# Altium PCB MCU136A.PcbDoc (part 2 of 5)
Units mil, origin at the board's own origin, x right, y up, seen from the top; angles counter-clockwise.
Board outline 3937.01 x 4724.41 mil, 4 copper layers (Top Layer, Signal Layer 1, Signal Layer 2, Bottom Layer), stack 60 mil thick; 390 components, 224 nets, 1130 pads, 1344 vias.
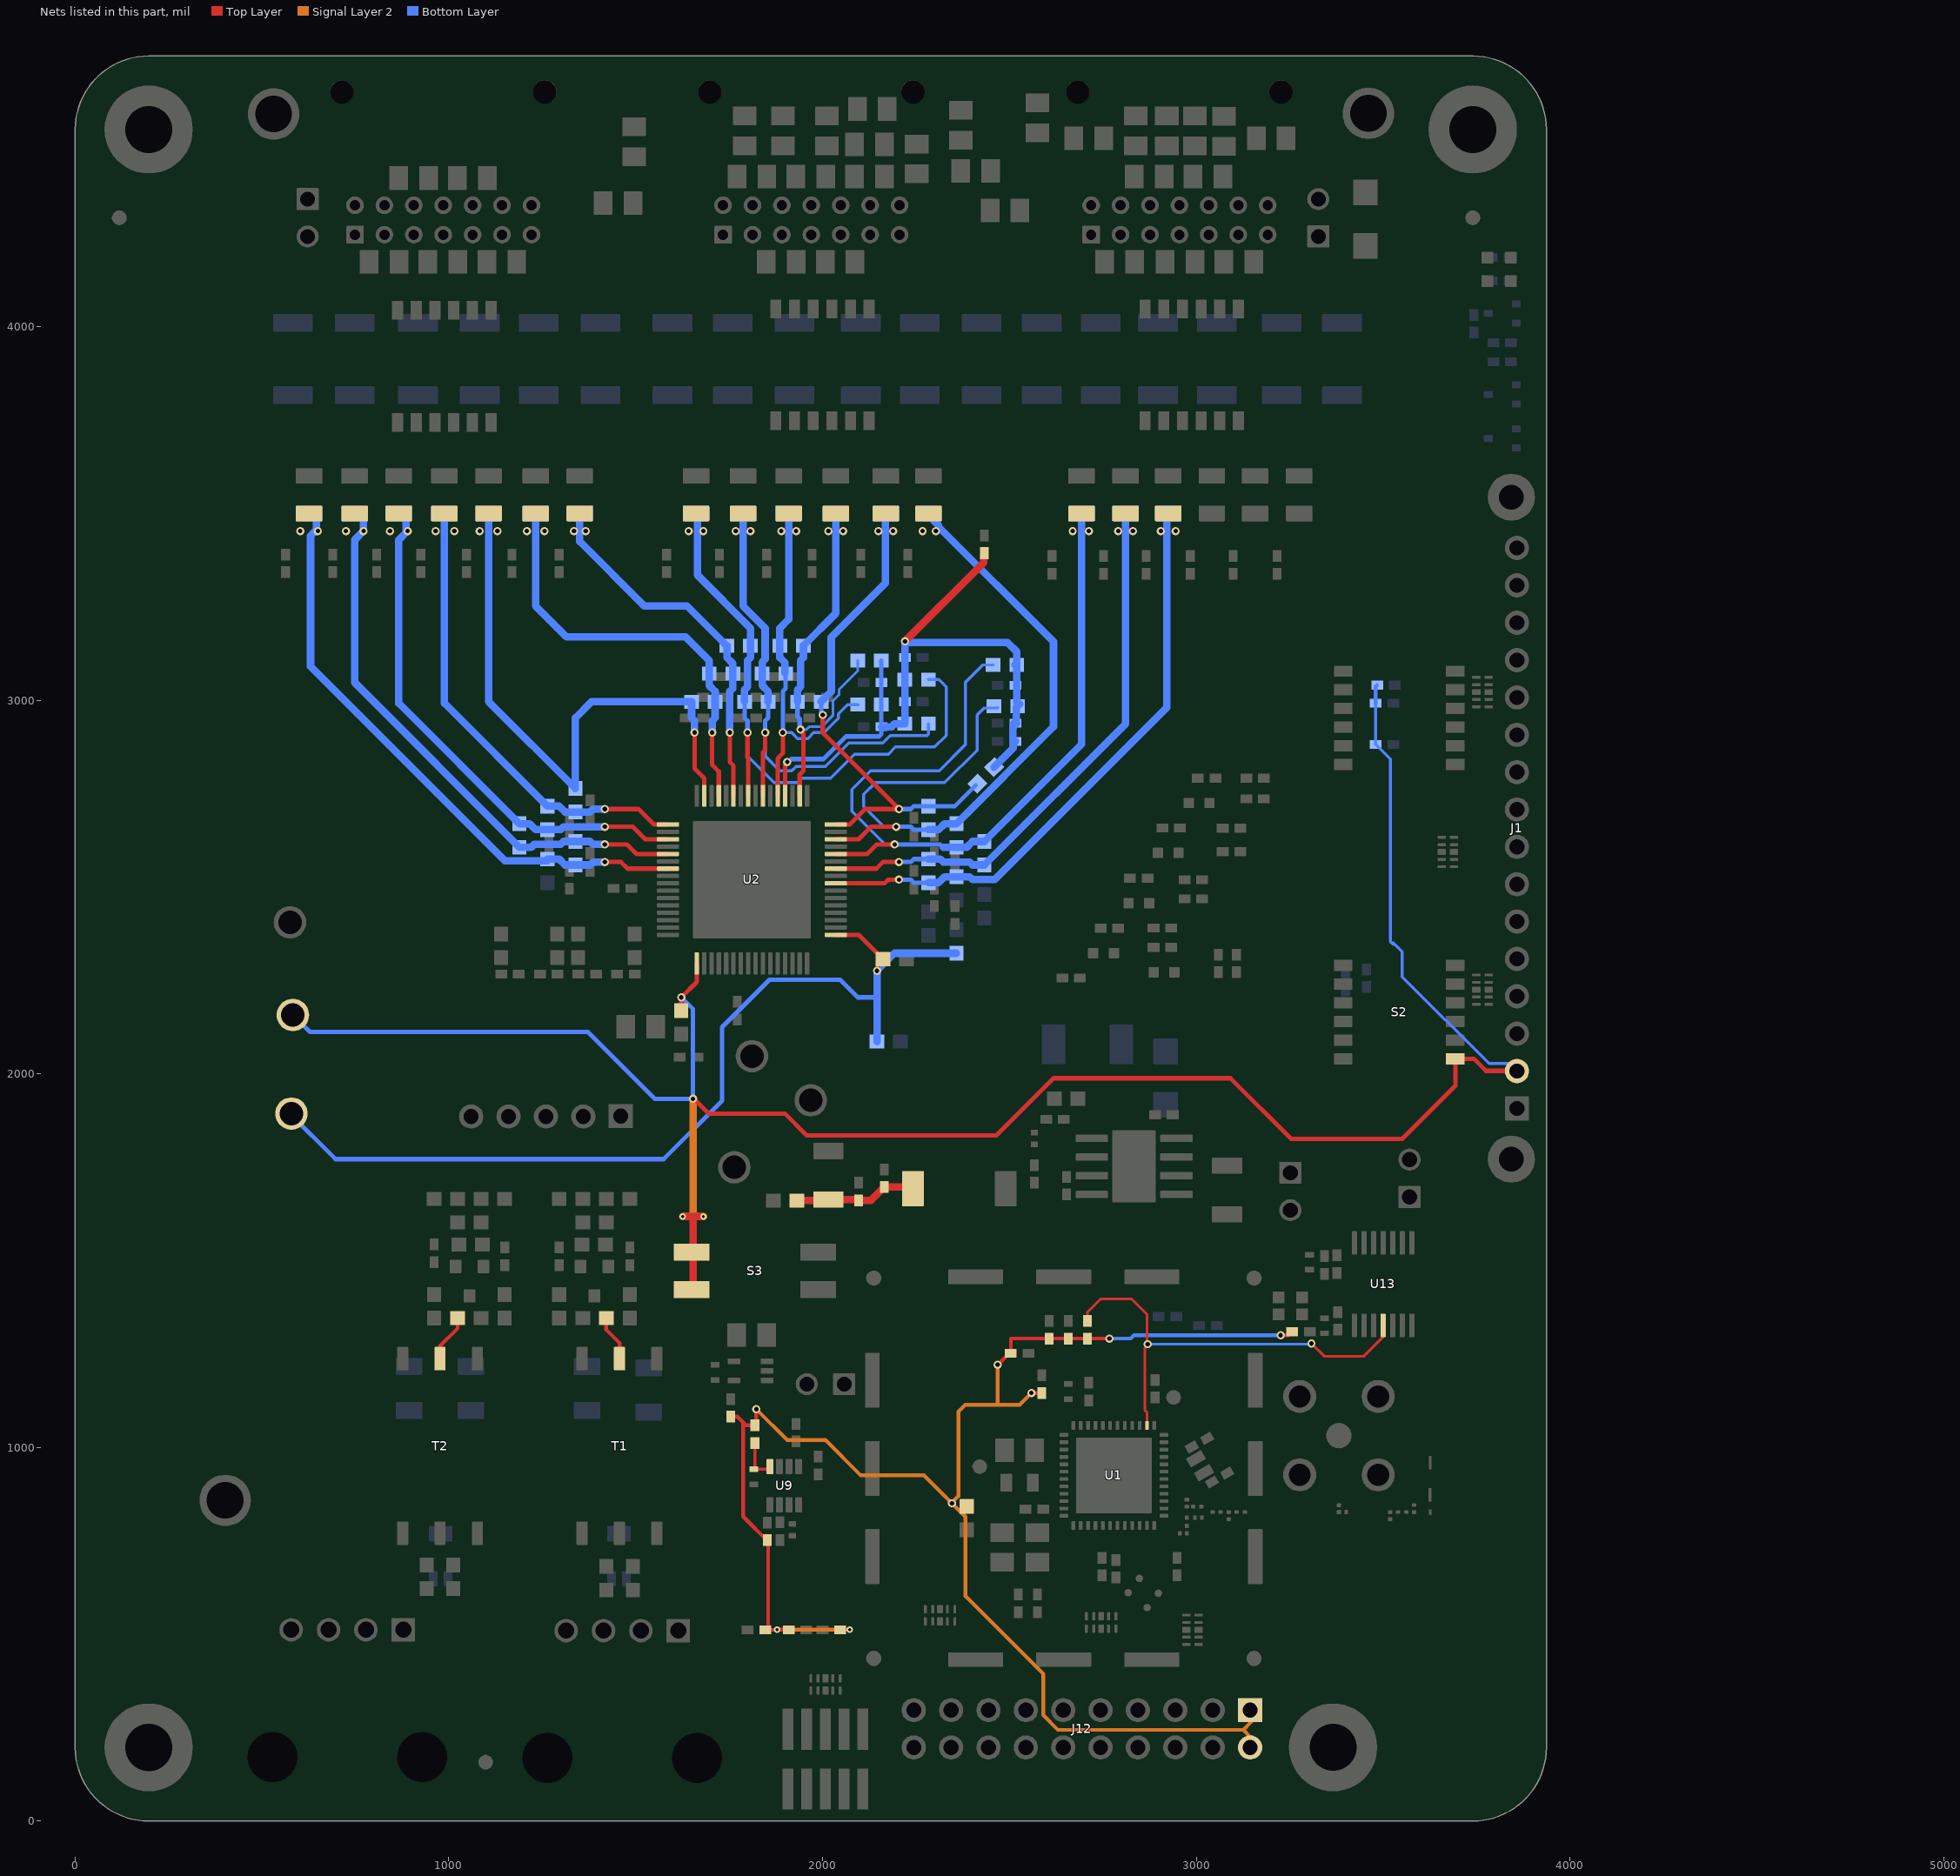
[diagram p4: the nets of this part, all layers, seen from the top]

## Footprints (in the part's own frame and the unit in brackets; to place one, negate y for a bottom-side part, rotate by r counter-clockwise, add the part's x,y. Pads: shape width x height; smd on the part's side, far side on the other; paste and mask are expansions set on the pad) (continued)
FP-SRR0735HA-820M-NO_KEEPOUTS-MFG [mm]
  rrect7% 1.5x2.4 smd paste+0 mask+0: 1(-3.15,0) 2(3.15,0)
  silkscreen extent -3.75,-3.75 3.75,3.75, body extent -3.65,-3.65 3.65,3.65, height 3.7
IEC_HighVoltage_Small [mil]
  silkscreen extent -107,-88 107,97
Keystone1598-2 [mm] "Triple Turret"
  round 3.5 hole 2.5: 1(0,0)
  silkscreen extent -2.08,-2.08 2.08,2.08, body extent -1.6,-1.6 1.59,1.6, height 7.72
Keystone5012 [mil] "Keystone Multipurpose loops"
  round 87 hole 63: 1(0,0)
  body extent -63,-63 63,62, height 319
Molex_70551-0038 [mm] "Header(shrouded), 2.54mm, 4x1, R/A, TH"
  rect 1.6x1.6 hole 1.09: 1(0,3.81)
  round 1.6 hole 1.09: 2(0,1.27) 3(0,-1.27) 4(0,-3.81)
  round 0 hole 3.4 unplated paste-2539.97 mask+0: MH1(8.64,-5.08) MH2(8.64,5.08)
  silkscreen extent 1.45,-6.98 12.88,7.32, body extent -0.71,-6.98 12.88,6.98, height 6.6
PAP0064F-MFG [mm]
  rrect33% 1.5x0.3 smd paste+0 mask+0: 1(-5.7,3.75) 2(-5.7,3.25) 3(-5.7,2.75) 4(-5.7,2.25) 5(-5.7,1.75) 6(-5.7,1.25) 7(-5.7,0.75) 8(-5.7,0.25) 9(-5.7,-0.25) 10(-5.7,-0.75) 11(-5.7,-1.25) 12(-5.7,-1.75) 13(-5.7,-2.25) 14(-5.7,-2.75) 15(-5.7,-3.25) 16(-5.7,-3.75) 33(5.7,-3.75) 34(5.7,-3.25) 35(5.7,-2.75) 36(5.7,-2.25) 37(5.7,-1.75) 38(5.7,-1.25) 39(5.7,-0.75) 40(5.7,-0.25) 41(5.7,0.25) 42(5.7,0.75) 43(5.7,1.25) 44(5.7,1.75) 45(5.7,2.25) 46(5.7,2.75) 47(5.7,3.25) 48(5.7,3.75)
  rrect33% 0.3x1.5 smd paste+0 mask+0: 17(-3.75,-5.7) 18(-3.25,-5.7) 19(-2.75,-5.7) 20(-2.25,-5.7) 21(-1.75,-5.7) 22(-1.25,-5.7) 23(-0.75,-5.7) 24(-0.25,-5.7) 25(0.25,-5.7) 26(0.75,-5.7) 27(1.25,-5.7) 28(1.75,-5.7) 29(2.25,-5.7) 30(2.75,-5.7) 31(3.25,-5.7) 32(3.75,-5.7) 49(3.75,5.7) 50(3.25,5.7) 51(2.75,5.7) 52(2.25,5.7) 53(1.75,5.7) 54(1.25,5.7) 55(0.75,5.7) 56(0.25,5.7) 57(-0.25,5.7) 58(-0.75,5.7) 59(-1.25,5.7) 60(-1.75,5.7) 61(-2.25,5.7) 62(-2.75,5.7) 63(-3.25,5.7) 64(-3.75,5.7)
  rrect1% 8x8 smd paste-1000 mask-1000: 65(0,0)
  silkscreen extent -7.12,-5.1 5.1,5.1, body extent -6.55,-6.55 6.55,6.55, height 0.25
PW0014A-MFG [mm]
  rrect29% 1.6x0.35 smd paste-1000 mask+0: 1(-2.8,1.95) 2(-2.8,1.3) 3(-2.8,0.65) 4(-2.8,0) 5(-2.8,-0.65) 6(-2.8,-1.3) 7(-2.8,-1.95) 8(2.8,-1.95) 9(2.8,-1.3) 10(2.8,-0.65) 11(2.8,0) 12(2.8,0.65) 13(2.8,1.3) 14(2.8,1.95)
  silkscreen extent -4.12,2.27 -3.88,2.52, body extent -3.7,-2.8 3.7,2.8, height 0.25
RGZ0048R-MFG [mm]
  rrect40% 0.6x0.25 smd paste+0 mask+0: 1(-3.4,2.75) 2(-3.4,2.25) 3(-3.4,1.75) 4(-3.4,1.25) 5(-3.4,0.75) 6(-3.4,0.25) 7(-3.4,-0.25) 8(-3.4,-0.75) 9(-3.4,-1.25) 10(-3.4,-1.75) 11(-3.4,-2.25) 12(-3.4,-2.75) 25(3.4,-2.75) 26(3.4,-2.25) 27(3.4,-1.75) 28(3.4,-1.25) 29(3.4,-0.75) 30(3.4,-0.25) 31(3.4,0.25) 32(3.4,0.75) 33(3.4,1.25) 34(3.4,1.75) 35(3.4,2.25) 36(3.4,2.75)
  rrect40% 0.25x0.6 smd paste+0 mask+0: 13(-2.75,-3.4) 14(-2.25,-3.4) 15(-1.75,-3.4) 16(-1.25,-3.4) 17(-0.75,-3.4) 18(-0.25,-3.4) 19(0.25,-3.4) 20(0.75,-3.4) 21(1.25,-3.4) 22(1.75,-3.4) 23(2.25,-3.4) 24(2.75,-3.4) 37(2.75,3.4) 38(2.25,3.4) 39(1.75,3.4) 40(1.25,3.4) 41(0.75,3.4) 42(0.25,3.4) 43(-0.25,3.4) 44(-0.75,3.4) 45(-1.25,3.4) 46(-1.75,3.4) 47(-2.25,3.4) 48(-2.75,3.4)
  rrect2% 5.15x5.15 smd paste-1000 mask+0: 49(0,0)
  silkscreen extent -4.05,-3.55 3.55,3.84, body extent -3.8,-3.8 3.8,3.8, height 0.25
Samtec_FTSH-105-01-x-DV-K [mm] "Header(Shrouded), 1.27mm, 5x2, SMT"
  rect 2.79x0.74 smd: 1(-2.035,2.54) 2(2.035,2.54) 3(-2.035,1.27) 4(2.035,1.27) 5(-2.035,0) 6(2.035,0) 7(-2.035,-1.27) 8(2.035,-1.27) 9(-2.035,-2.54) 10(2.035,-2.54)
  silkscreen extent -3.73,-3.48 3.73,3.48, body extent -2.92,-3.18 2.92,3.17, height 6.13
Samtec_SMA-J-P-H-ST-MT1 [mm] "JACK, SMA, 50 Ohm, TH"
  round 1.73 smd: 1(0,0)
  round 2.25 hole 1.5: 2(-2.665,2.665) 3(2.665,2.665) 4(-2.665,-2.665) 5(2.665,-2.665)
  body extent -3.17,-3.17 3.18,3.18, height 7.95
SNT-100-BK-G [mil] "Samtec STEP model"
  round 1 on Mech3: 0(0,0)
  body extent -100,-50 100,50, height 344
SOT-323 [mm] "Diodes Inc recommended land pattern.  2016-02-24"
  rrect21% 0.6x0.47 smd: 1(-0.95,0.65) 2(-0.95,-0.65) 3(0.95,0)
  silkscreen extent -1.14,-1.22 0.77,1.22, body extent -1.13,-1.13 1.12,1.12, height 1.13
SW_219-2MST [mm] "SMT, 4-Leads, Body 6.55x6.7mm, Pitch 2.54mm"
  rect 2.44x1.13 smd: 1(-4.3,1.27) 2(-4.3,-1.27) 3(4.3,-1.27) 4(4.3,1.27)
  body extent -4.95,-3.28 4.95,3.28, height 4.32
SW_TDA06H0SB1 [mil] "SMT, 12-Lead, Body 8.75x6.2mm, Pitch 1.27mm"
  rect 50x30 smd: 1(-150,125) 2(-150,75) 3(-150,25) 4(-150,-25) 5(-150,-75) 6(-150,-125) 7(150,-125) 8(150,-75) 9(150,-25) 10(150,25) 11(150,75) 12(150,125)
  silkscreen extent -126,-172 126,172, body extent -160,-172 160,172, height 91
TI_Horizontal_Overlay_Small [mil]
  silkscreen extent -545,-68 545,67
TP_SM_1MM#1 [mm] "1mm Test Point, SMT"
  round 1 smd paste-0.5: 1(0,-0.361)
TP_SM_1MM#2 [mm] "1mm Test Point, SMT"
  round 1 smd paste-0.5: 1(0,0.508)
TSW-105-07-X-S [mm] "Samtec 100mil, 1x5, 230 mil above insulator"
  rrect6% 1.65x1.65 hole 1.016: 1(-5.08,-0.025)
  round 1.65 hole 1.016: 2(-2.54,0) 3(0,0) 4(2.54,0) 5(5.08,0)
  silkscreen extent -7.05,-1.25 6.37,1.25, body extent -6.35,-1.27 6.35,1.27, height 8.38
TSW-110-07-G-D [mm] "Samtec 100mil, 2x10, 230 mil above insulator"
  rrect6% 1.65x1.65 hole 1.016: 1(-11.43,-1.27)
  round 1.65 hole 1.016: 2(-11.43,1.27) 3(-8.89,-1.27) 4(-8.89,1.27) 5(-6.35,-1.27) 6(-6.35,1.27) 7(-3.81,-1.27) 8(-3.81,1.27) 9(-1.27,-1.27) 10(-1.27,1.27) 11(1.27,-1.27) 12(1.27,1.27) 13(3.81,-1.27) 14(3.81,1.27) 15(6.35,-1.27) 16(6.35,1.27) 17(8.89,-1.27) 18(8.89,1.27) 19(11.43,-1.27) 20(11.43,1.27)
  silkscreen extent -13.73,-2.54 12.7,2.54, body extent -12.7,-2.54 12.7,2.54, height 8.38
TSW-116-07-G-S [mm] "Samtec 100mil, 1x16, 230 mil above insulator"
  rrect6% 1.65x1.65 hole 1.016: 1(-19.05,0)
  round 1.65 hole 1.016: 2(-16.51,0) 3(-13.97,0) 4(-11.43,0) 5(-8.89,0) 6(-6.35,0) 7(-3.81,0) 8(-1.27,0) 9(1.27,0) 10(3.81,0) 11(6.35,0) 12(8.89,0) 13(11.43,0) 14(13.97,0) 15(16.51,0) 16(19.05,0)
  silkscreen extent -20.39,-1.27 20.32,1.63, body extent -20.32,-1.27 20.32,1.27, height 8.38
WEEE_Minimum [mil] "WEEElie bin"
  silkscreen extent -95,-172 99,104
WL-SMCW_GREEN [mm] "WURTH"
  rect 0.8x0.8 smd: 1(-0.8,0) 2(0.8,0)
  silkscreen extent -1.9,-0.8 1.2,0.8, body extent -0.85,-0.45 0.85,0.45, height 0.8
WL-SMCW_RED [mm] "WURTH"
  rect 0.8x0.8 smd: 1(-0.8,0) 2(0.8,0)
  silkscreen extent -1.9,-0.8 1.2,0.8, body extent -0.85,-0.45 0.85,0.45, height 0.8

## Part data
C1 C8 C10 C15 C16: library part CMP-0006356-2, "CAP, CERM, 0.1 uF, 50 V, +/- 10%, X7R, AEC-Q200 Grade 1, 0402", Cap_Case=0402, Manufacturer=MuRata, Supplier Part Number 1=490-10672-1-ND, TempCo=X7R, Tolerance_%=10%, Value1=Unknown, Value2=50V, ValueDisplayed=0.1uF
C2: library part CMP-0006357-2, "CAP, CERM, 2200 pF, 50 V, +/- 10%, X7R, AEC-Q200 Grade 1, 0402", Cap_Case=0402, Manufacturer=MuRata, Supplier Part Number 1=490-4914-1-ND, TempCo=X7R, Tolerance_%=10%, Value1=Unknown, Value2=50V, ValueDisplayed=2200pF
C3: library part CMP-0096011-1, "Ceramic Capacitor for Automotive 47uF ±10% 10VDC X7S 1210 Embossed T/R", Manufacturer=Murata, Operating Temperature Range="-55°C to +125°C", TempCo=22%, Temperature Characteristic=X7S, Tolerance_%=10%, ValueDisplayed=47uF
C4: library part CMP-0093675-1, "4.7uF ±10% 100V Ceramic Capacitor X7S 1210 (3225 Metric)", Manufacturer=Murata, Operating Temperature Range="-55°C to +125°C", TempCo=22%, Temperature Characteristic=X7S, Tolerance_%=10%, ValueDisplayed=4.7uF
C5: library part CMP-0006359-2, "CAP, CERM, 3300 pF, 50 V, +/- 10%, X7R, AEC-Q200 Grade 1, 0402", Cap_Case=0402, Manufacturer=MuRata, Supplier Part Number 1=490-8001-1-ND, TempCo=X7R, Tolerance_%=10%, Value1=Unknown, Value2=50V, ValueDisplayed=3300pF
C6: library part CMP-0121510-1, "Ceramic Capacitor for Automotive 56pF ±1% 50VDC C0G 0402 Paper T/R", Manufacturer=Murata, Operating Temperature Range="-55°C to +125°C", TempCo=30ppm/°C, Temperature Characteristic=C0G, Tolerance_%=0.01%, ValueDisplayed=56pF
C7 C11: library part CMP-0084773-1, "CAP, CERM, 0.01 µF, 100 V,+/- 10%, X7R, AEC-Q200 Grade 1, 0603", Cap_Case=0603, Manufacturer=MuRata, TempCo=X7R, Tolerance_%=10%, Value2=100V, ValueDisplayed=0.01µF
C9 C14 C17: library part CMP-0064967-2, "CAP, CERM, 0.47 uF, 10 V,+/- 10%, X7S, 0402", Cap_Case=0402, Manufacturer=MuRata, Supplier Part Number 1=490-14427-1-ND, TempCo=X7S, Tolerance_%=10%, Value1=Unknown, Value2=10V, ValueDisplayed=0.47uF
C12: library part CMP-0860704-1, "CAP, CERM, 1 µF, 25 V,+/- 10%, X8L, AEC-Q200 Grade 0, 0805", Cap_Case=0805, Manufacturer=MuRata, TempCo=X8L, Tolerance_%=10%, Value2=25V, ValueDisplayed=1µF
C13: library part CMP-0007136-5, "CAP, CERM, 1 uF, 16 V, +/- 10%, X7R, AEC-Q200 Grade 1, 0603", Cap_Case=0603, Manufacturer=MuRata, Supplier Part Number 1=490-5241-6-ND, TempCo=X7R, Tolerance_%=10%, Value1=Unknown, Value2=16V, ValueDisplayed=1uF
C18 C19 C21 C23 C25 C27 C29 C31 C33 C35 C37 C42 C47 C48 C52 C57 C61 C63 C65 C67 C69: library part CMP-0007144-4, "CAP, CERM, 0.1 uF, 50 V, +/- 10%, X7R, 0603", Cap_Case=0603, Manufacturer=MuRata, Supplier Part Number 1=490-4779-1-ND, TempCo=X7R, Tolerance_%=10%, Value1="0.02 ohm", Value2=50V, ValueDisplayed=0.1uF
C20 C22 C24 C26 C28 C30 C32 C34 C36 C39 C44 C49 C50 C54 C58 C62 C64 C66 C68 C70: library part CMP-0006361-2, "CAP, CERM, 4700 pF, 50 V, +/- 10%, X7R, AEC-Q200 Grade 1, 0402", Cap_Case=0402, Manufacturer=MuRata, Supplier Part Number 1=490-4915-1-ND, TempCo=X7R, Tolerance_%=10%, Value1=Unknown, Value2=50V, ValueDisplayed=4700pF
C38 C41 C45 C51 C55 C60: library part CMP-0007144-4, "CAP, CERM, 0.1 uF, 50 V, +/- 10%, X7R, 0603", Cap_Case=0603, Manufacturer=MuRata, Supplier Part Number 1=490-4779-1-ND, TempCo=X7R, Tolerance_%=10%, Value1="0.02 ohm", Value2=50V, ValueDisplayed=DNP
C40 C43 C46 C53 C56 C59: library part CMP-0006361-2, "CAP, CERM, 4700 pF, 50 V, +/- 10%, X7R, AEC-Q200 Grade 1, 0402", Cap_Case=0402, Manufacturer=MuRata, Supplier Part Number 1=490-4915-1-ND, TempCo=X7R, Tolerance_%=10%, Value1=Unknown, Value2=50V, ValueDisplayed=DNP
C71 C76 C77 C82: library part CMP-0090879-1, "2200pF ±10% 2000V (2kV) Ceramic Capacitor X7R (2R1) 1206 (3216 Metric)", Digikey Part Number=1608-1486-1-ND, Manufacturer="Knowles Syfer", Mouser Part Number=843-1206Y2K00222KET, Operating Temperature Range="-55°C to +125°C", TempCo=15%, Temperature Characteristic=X7R, Tolerance_%=10%, ValueDisplayed=2.2nF
C72 C75 C78 C81: library part CMP-0006316-2, "CAP, CERM, 220 pF, 50 V, +/- 10%, X7R, AEC-Q200 Grade 1, 0402", Cap_Case=0402, Manufacturer=TDK, Supplier Part Number 1=445-6886-1-ND, TempCo=X7R, Tolerance_%=10%, Value1="9.829 ohm", Value2=50V, ValueDisplayed=220pF
C73 C79: library part CMP-0007143-4, "CAP, CERM, 0.01 uF, 50 V, +/- 10%, X7R, AEC-Q200 Grade 1, 0603", Cap_Case=0603, Manufacturer=MuRata, Supplier Part Number 1=490-4778-1-ND, TempCo=X7R, Tolerance_%=10%, Value1=Unknown, Value2=50V, ValueDisplayed=0.01uF
C74 C80: library part CMP-0750041-1, "CAP, CERM, 100 pF, 50 V,+/- 5%, C0G/NP0, AEC-Q200 Grade 1, 0603", Cap_Case=0603, Manufacturer=MuRata, TempCo=C0G/NP0, Tolerance_%=5%, Value2=50V, ValueDisplayed=100pF
C83: library part CMP-0120705-1, "Ceramic Capacitor for Automotive 47nF ±10% 25VDC X7R 0402 Paper T/R", Manufacturer=Murata, Operating Temperature Range="-55°C to +125°C", TempCo=15%, Temperature Characteristic=X7R, Tolerance_%=0.1%, ValueDisplayed=47nF
C84 C85 C88 C91 C108: library part CMP-0006349-2, "CAP, CERM, 1 uF, 10 V, +/- 10%, X7S, AEC-Q200 Grade 1, 0402", Cap_Case=0402, Manufacturer=MuRata, Supplier Part Number 1=81-GCM155C71A105KE8D, TempCo=X7S, Tolerance_%=10%, Value1=Unknown, Value2=10V, ValueDisplayed=1uF
C86: library part CMP-0006352-2, "CAP, CERM, 0.01 uF, 25 V, +/- 10%, X7R, 0402", Cap_Case=0402, Manufacturer=MuRata, Supplier Part Number 1=490-6043-2-ND, TempCo=X7R, Tolerance_%=10%, Value1=Unknown, Value2=25V, ValueDisplayed=0.01uF
C87: library part CMP-0083622-1, "CAP, CERM, 2.2 µF, 25 V,+/- 10%, X7R, AEC-Q200 Grade 1, 0805", Cap_Case=0805, Manufacturer=MuRata, Supplier Part Number 1=490-4787-1-ND, TempCo=X7R, Tolerance_%=10%, Value2=25V, ValueDisplayed=2.2µF
C89 C90 C103 C104 C105 C107 C109 C111 C112: library part CMP-0006350-2, "CAP, CERM, 0.1 uF, 10 V, +/- 10%, X7R, AEC-Q200 Grade 1, 0402", Cap_Case=0402, Manufacturer=MuRata, Supplier Part Number 1=81-GCM155R71A104K5D, TempCo=X7R, Tolerance_%=10%, Value1=Unknown, Value2=10V, ValueDisplayed=0.1uF
C92: library part CMP-0120430-1, "High Q Chip Multilayer Ceramic Capacitors for Automotive 12pF ±2% 50Vdc 0201", Manufacturer=Murata, Operating Temperature Range="-25°C to +125°C", TempCo=30ppm/°C, Temperature Characteristic=C0G, Tolerance_%=2%, ValueDisplayed=DNP
C93 C97: library part CMP-0120430-1, "High Q Chip Multilayer Ceramic Capacitors for Automotive 12pF ±2% 50Vdc 0201", Manufacturer=Murata, Operating Temperature Range="-25°C to +125°C", TempCo=30ppm/°C, Temperature Characteristic=C0G, Tolerance_%=2%, ValueDisplayed=12pF
C94 C95: library part CMP-0085816-1, "CAP, CERM, 12 pF, 50 V,+/- 5%, C0G/NP0, AEC-Q200 Grade 1, 0402", Cap_Case=0402, Manufacturer=MuRata, TempCo=C0G/NP0, Tolerance_%=5%, Value2=50V, ValueDisplayed=12pF
C96 C99 C101: library part CMP-0120431-1, "1pF ±0.05pF 50V Ceramic Capacitor C0G 0201 (0603 Metric)", Manufacturer=Murata, Operating Temperature Range="-55°C to +125°C", TempCo=30ppm/°C, Temperature Characteristic=C0G, ValueDisplayed=1pF
C98: library part CMP-0124483-1, "Cap Ceramic 1.1pF ±0.1pF 50V C0G 0201 AECQ200", Manufacturer=Murata, Operating Temperature Range="-55°C to +125°C", TempCo=30ppm/°C, Temperature Characteristic=C0G, ValueDisplayed=1.1pF
C100: library part CMP-0120431-1, "1pF ±0.05pF 50V Ceramic Capacitor C0G 0201 (0603 Metric)", Manufacturer=Murata, Operating Temperature Range="-55°C to +125°C", TempCo=30ppm/°C, Temperature Characteristic=C0G, ValueDisplayed=DNP
C102 C106 C110: library part CMP-0008015-1, "CAP, CERM, 22 uF, 6.3 V, +/- 20%, X7T, AEC-Q200 Grade 1, 0805", Cap_Case=0805, Manufacturer=MuRata, TempCo=X7T, Tolerance_%=20%, Value1=Unknown, Value2=6.3V, ValueDisplayed=22uF
D1 D4: library part CMP-0121790-1, "137V Clamp 2.9A Ipp Tvs Diode Surface Mount DO-214AC (SMA)", Breakdown Voltage=94.4V, Clamping Voltage=137V, Digikey Part Number=13-SMAJ85A-AT/TR13CT-ND, Manufacturer=YAGEO, Mouser Part Number=603-SMAJ85A-AT/TR13, Operating Temperature Range="-55°C to +150°C"
D2 D5: library part CMP-0002894-2, "LED, Green, SMD", Color=green, Manufacturer="Wurth Elektronik", Value1=W, Value2=2V
D3 D6: library part CMP-0002947-3, "LED, Red, SMD", Color=Red, Manufacturer="Wurth Elektronik", Power_TotalModule=72mW, Value1=0.072W, Value2=2V
E1: library part CMP-0001734-1, "2.4GHz PCB Antenna.  There is nothing to buy or mount.", Manufacturer=N/A
FID1 FID2 FID3 FID4 FID5 FID6: library part CMP-0077181-1, "Fiducial mark.  There is nothing to buy or mount.", Manufacturer=N/A
J1: library part CMP-0075430-1, "Header, 100mil, 16x1, Gold, TH", Color=Black, Current_A=6.3A, Manufacturer=Samtec, Supplier Part Number 1=SAM1029-16-ND, Voltage_V=550V
J2 J6 J11 J13 J14: library part CMP-0002337-1, "Header, 100mil, 2x1, Tin, TH", Color=Black, Current_A=3A, Manufacturer="Sullins Connector Solutions", Supplier Part Number 1=S1012E-02-ND, Voltage_V=1.8kV
J3 J4 J5: library part CMP-0096844-1, "14 Position Dual Row Side Entry 2 mm Through Hole Shrouded Header", Current_A=3A, Digikey Part Number=455-2488-ND, Manufacturer=JST, Operating Temperature Range="-25°C to +85°C", Voltage_V=250V
J7 J9: library part CMP-0055239-1, "Header(shrouded), 2.54mm, 4x1, R/A, Gold, TH", Color=Black, Current_A=3A, Manufacturer=Molex, Supplier Part Number 1=0705510038-ND, Voltage_V=250V
J8: library part CMP-0075411-1, "Header, 100mil, 5x1, Gold, TH", Color=Black, Current_A=6.3A, Manufacturer=Samtec, Supplier Part Number 1=SAM1029-05-ND, Voltage_V=550V
J10: library part CMP-0075670-2, "Header (Shrouded), 1.27mm, 5x2, Gold, SMT", Color=Black, Current_A=3.3A, Manufacturer=Samtec, Supplier Part Number 1=SAM8796-ND
J12: library part CMP-0075421-2, "Header, 100mil, 10x2, Gold, TH", Color=Black, Current_A=6.3A, Manufacturer=Samtec, Supplier Part Number 1=SAM1028-10-ND, Voltage_V=550V
J15: library part CMP-0080462-1, "JACK, SMA, 50 Ohm, Gold, TH", Color=Gold, Manufacturer=Samtec, Supplier Part Number 1=SAM10718-ND, Voltage_V=335V
L1: library part CMP-0125208-2, "82 µH Shielded Drum Core, Wirewound Inductor 630 mA 480mOhm Max Nonstandard", Alternate Manufacturer=Bourns, Alternate PartNumber=SRR0735A-820M, Digikey Part Number=118-SRR0735HA-820MTR-ND, Mouser Part Number=652-SRR0735HA-820M, Operating Temperature Range="-55°C to +150°C", Test Frequency=1kHz, Tolerance_%=20%
L2 L3: library part CMP-0093758-1, "100 µH @ 100 kHz 2 Line Common Mode Choke Surface Mount 150mA DCR 1.5Ohm", Digikey Part Number=445-175063-1-ND, Manufacturer=TDK, Mouser Part Number=810-ACT1210R-101-2P, Operating Temperature Range="-40°C to +125°C", Test Frequency=100kHz, Tolerance_%=+50/-30%
L4 L8: library part CMP-0090225-1, "Inductor 3.7nH, Size Code 0603 (0201), High Q, Wide Variation. AEC-Q200", Manufacturer=Murata, Operating Temperature Range="-55°C to +125°C", Self Resonant Frequency=6GHz, Test Frequency=500MHz, Tolerance_%=0.1nH
L5: library part CMP-0124485-1, "Film type RF Inductor for Automotive 2.2nH ±0.1nH 600mA 0.15Ω 0201 (0603)", Manufacturer=Murata, Operating Temperature Range="-55°C to +125°C", Self Resonant Frequency=11GHz, Test Frequency=500MHz, Tolerance_%=0.1nH
L6 L7: library part CMP-0037178-1, "Film type RF Inductor for Automotive 3.4nH ±0.1nH 450mA 0.25Ω 0201 (0603)", Manufacturer=Murata, Operating Temperature Range="-55°C to +125°C", Self Resonant Frequency=7GHz, Test Frequency=500MHz, Tolerance_%=0.1nH
L9: library part CMP-0080768-1, "Ferrite Bead, 1500 ohm @ 100 MHz, 0.5 A, 0603", Manufacturer=MuRata, Supplier Part Number 1=490-16502-1-ND, Value1="0.5 ohm", Value2=0.5A, ValueDisplayed="1500 ohm"
L10: library part CMP-0121210-1, "Shielded Multilayer Inductor 6.8uH ±20% 550mA 325mΩ AEC-Q200 SMD 0805", Manufacturer=TDK, Operating Temperature Range="-55°C to +125°C", Test Frequency=2MHz, Tolerance_%=20%
Logo1: library part CMP-0074838-1, "Texas Instrument Corporate Signature"
Logo2: library part CMP-0074769-1
Logo4: library part CMP-0074847-1, "FCC_disclaimer"
Logo5: library part CMP-0074840-1, "ESD Susceptible Symbol"
Logo6: library part CMP-0074835-1, "IEC 61010-1 High Voltage Warning"
MP1 MP2 MP3 MP4: library part CMP-0016301-1, "Spacer Support Nylon 66 Natural", Manufacturer="Kang Yang USA", Operating Temperature Range=to
MP5: library part CMP-0120478-1, "RF Shield Cover 1.058\" (26.87mm) X 1.058\" (26.87mm) Non-Vented Surface Mount", Digikey Part Number=1798-1210-ND, Manufacturer="Leader Tech", Mouser Part Number=861-SMS-403C, Operating Temperature Range=to
MP6: library part CMP-0086879-1, "RF SHIELD 1.034\" X 1.034\" SMD", Manufacturer="Leader Tech"
Q1 Q2 Q3: library part CMP-0000776-1, "MOSFET, N-CH, 60 V, 0.115 A, SOT-323", Alternate Manufacturer=None, Manufacturer="Diodes Inc.", Supplier Part Number 1=2N7002W-FDICT-ND, Value1=7
R1 R2 R9 R11 R14 R15 R16 R19 R22 R25 R27 R145 R147 R148: library part CMP-0025958-3, "RES, 10.0 k, 1%, 0.063 W, AEC-Q200 Grade 0, 0402", Manufacturer=Vishay-Dale, Power_W=63mW, Supplier Part Number 1=541-10.0KLCT-ND, TempCo="100 ppm/C", Tolerance_%=1%, Value2=0.063W, Value_Code=10k0, ValueDisplayed=10.0k
R3 R119 R121 R126 R128 R130 R132 R137 R139: library part CMP-0025697-4, "RES, 0, 5%, 0.1 W, AEC-Q200 Grade 0, 0603", Manufacturer=Vishay-Dale, Power_W=100mW, Supplier Part Number 1=541-0.0GCT-ND, TempCo="200 ppm/C", Tolerance_%=5%, Value2=0.1W, Value_Code=0000, ValueDisplayed=0
R4: library part CMP-0016161-3, "RES, 5.1, 5%, 0.75 W, AEC-Q200 Grade 0, 2010", Manufacturer=Vishay-Dale, Power_W=750mW, Supplier Part Number 1=541-5.1WCT-ND, TempCo="200 ppm/C", Tolerance_%=5%, Value2=0.75W, Value_Code=5R10, ValueDisplayed=5.1
R5 R6 R141 R144 R146 R149 R150: library part CMP-0026822-3, "RES, 0, 5%, 0.063 W, AEC-Q200 Grade 0, 0402", Manufacturer=Vishay-Dale, Power_W=63mW, Supplier Part Number 1=541-0.0JCT-ND, TempCo="200 ppm/C", Tolerance_%=5%, Value2=0.063W, Value_Code=0000, ValueDisplayed=0
R7: library part CMP-0025967-3, "RES, 110 k, 1%, 0.063 W, AEC-Q200 Grade 0, 0402", Manufacturer=Vishay-Dale, Power_W=63mW, Supplier Part Number 1=541-110KLCT-ND, TempCo="100 ppm/C", Tolerance_%=1%, Value2=0.063W, Value_Code=110k
R8: library part CMP-0026415-2, "RES, 4.02 M, 1%, 0.063 W, AEC-Q200 Grade 0, 0402", Manufacturer=Vishay-Dale, Power_W=63mW, Supplier Part Number 1=541-4.02MLCT-ND, TempCo="100 ppm/C", Tolerance_%=1%, Value2=0.063W, Value_Code=4M02, ValueDisplayed=4.02M
R10: library part CMP-0026100-2, "RES, 1.00 M, 1%, 0.063 W, AEC-Q200 Grade 0, 0402", Manufacturer=Vishay-Dale, Power_W=63mW, Supplier Part Number 1=541-1.00MLCT-ND, TempCo="100 ppm/C", Tolerance_%=1%, Value2=0.063W, Value_Code=1M00, ValueDisplayed=1.00M
R12: library part CMP-0078244-2, "RES, 30.0 k, 1%, 0.063 W, AEC-Q200 Grade 0, 0402", Manufacturer=Vishay-Dale, Power_W=63mW, Supplier Part Number 1=541-30.0KLCT-ND, TempCo="100 ppm/C", Tolerance_%=1%, Value2=0.063W, Value_Code=30k0, ValueDisplayed=30.0k
R13: library part CMP-0022533-4, "RES, 60.4, 1%, 0.1 W, AEC-Q200 Grade 0, 0603", Manufacturer=Vishay-Dale, Power_W=100mW, Supplier Part Number 1=541-60.4HCT-ND, TempCo="100 ppm/C", Tolerance_%=1%, Value2=0.1W, Value_Code=60R4, ValueDisplayed=60.4
R17 R18 R24 R26 R142 R143 R153 R155 R156 R157: library part CMP-0025950-3, "RES, 100 k, 1%, 0.063 W, AEC-Q200 Grade 0, 0402", Manufacturer=Vishay-Dale, Power_W=63mW, Supplier Part Number 1=541-100KLCT-ND, TempCo="100 ppm/C", Tolerance_%=1%, Value2=0.063W, Value_Code=100k
R20 R21 R23: library part CMP-0026918-5, "RES, 3.3 k, 5%, 0.063 W, AEC-Q200 Grade 0, 0402", Manufacturer=Vishay-Dale, Power_W=63mW, Supplier Part Number 1=541-3.3KJCT-ND, TempCo="200 ppm/C", Tolerance_%=5%, Value2=0.063W, Value_Code=3k30, ValueDisplayed=3.3k
R28 R30 R31 R33 R34 R36 R37 R39 R40 R42 R43 R47 R50 R52 R55 R59 R62 R64 R65 R68 R69 R71 R74 R78 R81 R83 R86 R89 R91 R93 R94 R96 R97 R99 R101 R104 R106 R108: library part CMP-0121789-1, "RES Thick Film, 18Ω, 1%, 0.25W, 100ppm/°C, 1206", Manufacturer=Vishay, Operating Temperature Range="-55°C to +155°C", Power_W=250mW, TempCo=100ppm/°C, Tolerance_%=1%
R29 R32 R35 R38 R41 R46 R51 R58 R63 R67 R70 R77 R82 R88 R92 R95 R98 R103 R107: library part CMP-0026071-3, "RES, 1.00 k, 1%, 0.063 W, AEC-Q200 Grade 0, 0402", Manufacturer=Vishay-Dale, Power_W=63mW, Supplier Part Number 1=541-1.00KLCT-ND, TempCo="100 ppm/C", Tolerance_%=1%, Value2=0.063W, Value_Code=1k00, ValueDisplayed=1.00k
R44 R48 R53 R56 R60 R72 R75 R79 R84 R112 R113 R114 R116 R117 R118: library part CMP-0020442-3, "RES, 0, 5%, 0.125 W, AEC-Q200 Grade 0, 0805", Manufacturer=Vishay-Dale, Power_W=125mW, Supplier Part Number 1=541-0.0ACT-ND, TempCo="200 ppm/C", Tolerance_%=5%, Value2=0.125W, Value_Code=0000, ValueDisplayed=DNP
R45 R49 R54 R57 R61 R73 R76 R80 R85 R87 R90 R100 R102 R105 R109 R110 R111 R115: library part CMP-0020442-3, "RES, 0, 5%, 0.125 W, AEC-Q200 Grade 0, 0805", Manufacturer=Vishay-Dale, Power_W=125mW, Supplier Part Number 1=541-0.0ACT-ND, TempCo="200 ppm/C", Tolerance_%=5%, Value2=0.125W, Value_Code=0000, ValueDisplayed=0
R66: library part CMP-0026436-2, "RES, 511, 1%, 0.063 W, AEC-Q200 Grade 0, 0402", Manufacturer=Vishay-Dale, Power_W=63mW, Supplier Part Number 1=541-511LCT-ND, TempCo="100 ppm/C", Tolerance_%=1%, Value2=0.063W, Value_Code=511R, ValueDisplayed=511
R120 R127 R131 R138: library part CMP-0026438-2, "RES, 51.1, 1%, 0.063 W, AEC-Q200 Grade 0, 0402", Manufacturer=Vishay-Dale, Power_W=63mW, Supplier Part Number 1=541-51.1LCT-ND, TempCo="100 ppm/C", Tolerance_%=1%, Value2=0.063W, Value_Code=51R1, ValueDisplayed=51.1
R122 R129 R133 R140: library part CMP-0025885-5, "RES, 0, 5%, 0.1 W, 0603", Manufacturer=Yageo, Power_W=100mW, Supplier Part Number 1=311-0.0GRCT-ND, TempCo="200 ppm/C", Tolerance_%=5%, Value2=0.1W, Value_Code=0000, ValueDisplayed=DNP
R123 R125 R134 R136: library part CMP-0022446-5, "RES, 499, 1%, 0.1 W, AEC-Q200 Grade 0, 0603", Manufacturer=Vishay-Dale, Power_W=100mW, Supplier Part Number 1=541-499HCT-ND, TempCo="100 ppm/C", Tolerance_%=1%, Value2=0.1W, Value_Code=499R, ValueDisplayed=499
R124 R135: library part CMP-0022109-5, "RES, 1.00 k, 1%, 0.1 W, AEC-Q200 Grade 0, 0603", Manufacturer=Vishay-Dale, Power_W=100mW, Supplier Part Number 1=541-1.00KHCT-ND, TempCo="100 ppm/C", Tolerance_%=1%, Value2=0.1W, Value_Code=1k00, ValueDisplayed=DNP
R151 R152: library part CMP-0026890-5, "RES, 2.2 k, 5%, 0.063 W, AEC-Q200 Grade 0, 0402", Manufacturer=Vishay-Dale, Power_W=63mW, Supplier Part Number 1=541-2.2KJCT-ND, TempCo="200 ppm/C", Tolerance_%=5%, Value2=0.063W, Value_Code=2k20, ValueDisplayed=2.2k
R154 R158: library part CMP-0026823-3, "RES, 100 k, 5%, 0.063 W, AEC-Q200 Grade 0, 0402", Manufacturer=Vishay-Dale, Power_W=63mW, Supplier Part Number 1=541-100KJCT-ND, TempCo="200 ppm/C", Tolerance_%=5%, Value2=0.063W, Value_Code=100k
R159 R160 R161 R162 R163 R164 R165 R166 R167 R168 R169 R170 R171 R172 R173 R174 R175 R176: library part CMP-0121409-1, "RES Thick Film, 100Ω, 1%, 1W, 100ppm/°C, 2010", Manufacturer="Vishay Dale", Operating Temperature Range="-55°C to +155°C", Power_W=1W, TempCo=100ppm/°C, Tolerance_%=1%
RT1 RT2 RT3 RT4 RT5: library part CMP-0124490-2, "NTC Thermistor 10k 0603 (1608 Metric)", B Tolerance=1%, Digikey Part Number=445-NTCGS163JF103FT7CT-ND, Manufacturer=TDK, Max Current=0.31mA, Mouser Part Number=810-NTCGS163JF103FT7, Operating Temperature Range="-55°C to +125°C", Power_W=100mW
S1 S2 S4 S5 S6: library part CMP-0002278-1, "DIP Switch, SPST, 6Pos, Slide, SMT", CurrentRating_mA=25A, Manufacturer="C&K Components", Supplier Part Number 1=CKN9066-ND
S3: library part CMP-0002290-1, "Switch, SPST, Slide, Off-On, 2 Pos, 0.1A, 20V, SMD", CurrentRating_mA=100A, Manufacturer="CTS Electrocomponents", Supplier Part Number 1=CT2192MST-ND
SH-J1 SH-J2 SH-J3 SH-J4 SH-J5: library part CMP-0003623-3, "Shunt, 100mil, Gold plated, Black", Alternate Manufacturer=3M, Alternate PartNumber=969102-0000-DA, Manufacturer=Samtec, Supplier Part Number 1=SAM8858-ND
T1 T2: library part CMP-0086619-1, "BMS TRANSFORMER", Manufacturer=Pulse
TP1 TP8 TP9: library part CMP-0055121-1, "Terminal, Turret, TH, Triple", Manufacturer=Keystone, PartNumber=1598-2, Supplier Part Number 1=36-1598-2-ND
TP2 TP3 TP4 TP5 TP6 TP7: library part CMP-0055149-1, "Test Point, Multipurpose, White, TH", Color=White, Manufacturer=Keystone, PartNumber=5012, Supplier Part Number 1=36-5012-ND
TP10 TP11: library part CMP-0003825-1, "1mm Test Point, SMT", Manufacturer=Any
U1: library part CMP-0121950-1, "Automotive qualified SimpleLink wireless MCU for use in wireless battery management systems", Digikey Part Number=296-CC2662R1FTWRGZRQ1CT-ND, Frequency_Fixed=48MHz, Manufacturer="Texas Instruments", Max Supply Voltage=3.63V, Min Supply Voltage=1.8V, Mouser Part Number=595-C2662R1FTWRGZRQ1, Operating Temperature Range="-40°C to +105°C"
U2: library part CMP-0091255-1, "BQ79718-Q1", Manufacturer="Texas Instruments", Operating Temperature Range="-40°C to +125°C"
U3 U4 U5 U8 U11 U12 U14: library part CMP-0073599-3, "Automotive 4-Channel ESD Protection Solution for SuperSpeed (up to 5 Gbps) Interface, DQA0010A (USON-10)", Alternate Manufacturer="Texas Instruments"
U6 U7: library part CMP-0125207-1, "ESD Suppressor Diode TVS Bi-Dir 24V 70Vc Automotive AEC-Q101 3-Pin SOT-23 T/R", Breakdown Voltage=25.4V, Clamping Voltage=70V, Digikey Part Number=DESD1CAN2SOQ-7DICT-ND, Manufacturer="Diodes Inc.", Mouser Part Number=621-DESD1CAN2SOQ-7, Operating Temperature Range="-65°C to +150°C", ValueDisplayed=11pF
U9: library part CMP-0120735-1, "Automotive Nano IQ Precision Window Watchdog Timer", Manufacturer="Texas Instruments", Max Supply Voltage=6V, Min Supply Voltage=900mV, Nominal Supply Current=0.25uA, Operating Temperature Range="-40°C to +125°C", Output Voltage=0-6V
U10: library part CMP-0035727-2, "Single Output Automotive LDO, 50 mA, Fixed 3.3 V Output, 3 to 24 V Input, 5-pin SC70 (DCK), -40 to 125 degC, Green (RoHS & no Sb/Br)", Manufacturer="Texas Instruments"
U13: library part CMP-0120806-1, "Automotive 4-Bit Fixed Direction Voltage-Level Translator with SchmittTrigger Inputs and 3-State Outputs", Digikey Part Number=296-TXU0204QPWRQ1CT-ND, Manufacturer="Texas Instruments", Mouser Part Number=595-TXU0204QPWRQ1, Nominal Supply Current=2.5uA, Operating Temperature Range="-40°C to +125°C"
U15: library part CMP-0092718-1, "0.3-A,120-V, Step-Down Converter with Fly-buck Capability", Manufacturer="Texas Instruments", Max Supply Voltage=115V, Min Supply Voltage=6V, Nominal Supply Current=10-420uA, Operating Temperature Range="-40°C to +150°C", Switching Frequency=1MHz
Y1: library part CMP-0121920-1, "SMD Tuning Fork Crystal Resonators / kHz Band Crystal Resonators 32.768KHZ 7PF ±20PPM", Frequency Tolerance=20ppm, Frequency_Fixed=32.768kHz, Load Capacitance=7pF, Manufacturer=DAISHINKU, Operating Temperature Range="-40°C to +125°C"
Y2: library part CMP-0121714-1, "Quartz Crystal 48 MHz 7pF 10ppm", Frequency Stability=20ppm, Frequency Tolerance=10ppm, Frequency_Fixed=48MHz, Load Capacitance=7pF, Manufacturer="KYOCERA AVX", Operating Temperature Range="-40°C to +105°C"
ZZ1: library part CMP-0077236-1
ZZ2: library part CMP-0077237-1
ZZ3: library part CMP-0077238-1
ZZ4: library part CMP-0077238-1, "These assemblies must comply with workmanship standards IPC-A-610 Class 2, unless otherwise specified."

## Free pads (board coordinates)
  round 236.22 hole 125.98: 0(196.85,196.85) 0(196.85,4527.56) 0(3366.32,197) 0(3740.16,4527.56)
  round 125.98 hole 66.93: 0(3843.27,1771.65) 0(3843.27,3543.31)

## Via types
v1: diameter 22, hole 12, Top Layer to Bottom Layer, tented both sides, 890 vias
v2: diameter 22.01, hole 12.01, Top Layer to Bottom Layer, tented both sides, 402 vias
v3: diameter 19.68, hole 7.87, Top Layer to Bottom Layer, tented both sides, 21 vias
v4: diameter 24, hole 8, Top Layer to Bottom Layer, tented both sides, 12 vias
v5: diameter 20, hole 10, Top Layer to Bottom Layer, tented both sides, 7 vias
v6: diameter 24.8, hole 12.99, Top Layer to Bottom Layer, tented bottom, 6 vias
v7: diameter 17.46, hole 7.87, Top Layer to Bottom Layer, tented both sides, 6 vias

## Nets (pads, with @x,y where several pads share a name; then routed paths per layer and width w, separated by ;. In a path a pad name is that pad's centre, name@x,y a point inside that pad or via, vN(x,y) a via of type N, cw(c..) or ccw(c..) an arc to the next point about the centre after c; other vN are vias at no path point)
3V3_CC: J12.1 J12.2 L9.1 R141.1 R142.2 R143.2 R144.1 R145.2 R146.2 R149.2 R153.2 R154.2 R155.2 R156.2 R157.2 | length 4371.2
  Top Layer w10: R146.2@1754.15,1082.36 1771.97,1082.36 1787.4,1066.93 ; v1(1822.83,1102.36) 1822.83,1062.99 R144.1@1818.9,1059.06 1795.28,1059.06 1787.4,1066.93 ; R145.2@1854.33,751.84 R145.2@1854.33,748.03 ; R142.2@1893.91,511.81 1854.33,511.81 R145.2@1854.33,748.03 ; R143.2@2047.24,511.81 v7@2072.02,511.81 ; v1(2468.5,1221.29) 2469.32,1221.29 2500,1251.97 R156.2@2503.94,1251.97 2503.94,1291.34 v2(2767.72,1291.34) ; v2(2559.06,1145.67) R157.2@2586.61,1145.67 ; v2(3225.94,1300.28) 3247.42,1300.28 R149.2@3256.57,1309.42 ; 1787.4,1066.93 1787.4,814.96 R145.2@1854.33,748.03
  Signal Layer 2 w10: v1@1823.35,1101.85 1905.51,1019.68 2007.87,1019.68 2102.36,925.2 2271.65,925.2 v1(2346.46,850.39) 2346.46,852.53 2363.78,869.84 2363.78,1096.06 2381.89,1114.17 2468.5,1114.17 ; v7(1877.95,512.43) v7@2073.71,512.43 ; v1@2350.39,846.46 2382.19,814.67 2382.19,602.07 2590.55,393.7 2590.55,283.46 2629.92,244.09 3125.98,244.09 ; v1(2468.5,1221.29) 2468.5,1114.17 ; v2@2557.57,1144.18 2527.56,1114.17 2468.5,1114.17 ; J12.2@3145.67,196.85 3145.67,224.41 3125.98,244.09 ; J12.1@3145.67,295.28 3145.67,263.78 3125.98,244.09
  Bottom Layer w10: v2(2767.72,1291.34) 2824.65,1291.34 2833.59,1300.28 v2(3225.94,1300.28)
  other v7: 2072.33,511.81
3V3_WD: C84.1 R144.2 U9.8 | length 113.3
  Top Layer w8: R144.2@1818.9,1011.81 1818.9,944.76 C84.1@1822.71,940.94 ; C84.1@1823.11,941.26 1854.39,941.26 1859.25,946.12 U9.8@1859.25,948.82
AVDD: C13.1 J1.2 R16.1 R17.2 R18.2 S2.7 S3.1 S3.2 TP5.1 U2.49 | length 5952.1
  Top Layer w11.81: C13.1@1622.05,2169.29 v2(1622.05,2204.72) 1663.39,2246.06 U2.49@1663.39,2295.28 ; v1@1659.47,1929.13 1694.9,1893.7 1899.2,1893.7 1958.26,1834.65 2464.57,1834.65 2618.11,1988.19 3091.3,1988.19 3253.43,1826.06 3551.45,1826.06 3693.31,1967.92 S2.7@3693.31,2040.35 3743.11,2040.35 3775.59,2007.87 3858.27,2007.87 J1.2@3858.3,2007.48
  Top Layer w20: v7(1625.98,1618.11) 1653.54,1618.11 ; S3.2@1653.54,1421.26 S3.1@1653.54,1519.68 ; S3.1@1653.54,1522.44 1653.54,1618.11 ; v7(1681.1,1618.11) 1653.54,1618.11
  Signal Layer 2 w20: v7(1625.98,1618.11) 1653.54,1618.11 ; v1(1653.54,1933.07) 1653.54,1618.11 ; v7(1681.1,1618.11) 1653.54,1618.11
  Bottom Layer w8: R17.2@3480.31,2992.13 3480.31,2937.01 R18.2@3480.31,2881.89 3519.41,2842.8 3519.41,2354.27 3527.22,2346.46 3527.56,2346.46 ; 3527.56,2350.39 3551.18,2326.77 3551.18,2259.84 3783.46,2027.56 3838.19,2027.56 J1.2@3858.3,2007.48
  Bottom Layer w10: R17.2@3480.31,2992.13 3480.31,3036.59 R16.1@3484.25,3040.53
  Bottom Layer w11.81: TP5.1@582.68,2157.48 627.96,2112.2 1372.05,2112.2 1551.18,1933.07 v1(1653.54,1933.07) 1653.54,2173.23 v2(1622.05,2204.72)
BAT: C11.1 C18.1 R13.2 TP2.1 U2.1 | length 2568.5
  Top Layer w11.81: U2.1@2035.43,2372.05 2096.46,2372.05 2147.64,2320.87 2147.64,2319.88 2160.43,2307.09 C11.1@2161.42,2307.09 2156.99,2302.66 2149.61,2295.28 2148.62,2295.28 2147.64,2294.29 2147.64,2280.32 2145.67,2278.35 v2(2145.67,2275.59)
  Bottom Layer w11.81: TP2.1@574.99,1893.52 696.85,1771.65 1574.8,1771.65 1731.02,1927.87 1731.02,2124.72 1858.27,2251.97 2047.24,2251.97 2094.49,2204.72 2145.67,2204.72
  Bottom Layer w20: R13.2@2145.67,2086.61 2145.67,2204.72 2145.67,2276.13 2192.37,2322.83 C18.1@2358.27,2322.83
BB: C38.1 C40.2 C41.1 C43.2 C45.1 C46.2 C48.1 C50.2 C51.1 C53.2 C55.1 C56.2 C59.2 C60.1 R66.1 U2.20 | length 1828
  Top Layer w11.81: U2.20@1899.61,2744.09 v2@1899.61,2825.98
  Top Layer w20: v2@2220.86,3157.86 2431.26,3368.27 2431.26,3391.89 R66.1@2433.07,3393.7
  Bottom Layer w11.81: v2(1905.51,2834.65) 1908.27,2834.65 1916.15,2842.52 2002.26,2842.52 2062.83,2903.09 2151.12,2903.09 2157.48,2909.45 C53.2@2157.48,2929.13 C50.2@2157.48,3047.24 C48.1@2157.48,3106.3
  Bottom Layer w20: C53.2@2157.48,2929.13 2185.04,2929.13 2192.91,2937.01 C55.1@2220.47,2937.01 C56.2@2220.47,2996.06 C60.1@2220.47,3055.12 C59.2@2220.47,3114.17 v2(2220.47,3157.48) 2223.85,3154.1 2495.5,3154.1 2519.68,3129.92 2519.68,3098.43 C38.1@2515.75,3094.49 ; C45.1@2459.28,2820.99 2510,2871.71 2510,2887.95 2511.81,2889.76 C46.2@2515.75,2889.76 ; C46.2@2509.69,2895.51 2509.69,2924.64 2510,2924.96 2510,2936.36 2511.81,2938.17 C43.2@2515.75,2938.17 ; C43.2@2519.69,2938.17 2518.88,2938.97 2518.88,2981.12 C41.1@2527.49,2989.74 ; C38.1@2519.69,3094.53 2519.68,2992.95 2522.9,2989.74 C41.1@2527.56,2989.74
BQ0_CT_H: C74.2 T1.2 | length 146
  Top Layer w10: C74.2@1421.26,1346.46 1421.26,1314.96 1456.69,1279.53 T1.2@1456.06,1215.11
BQ0_CT_L: C80.2 T2.2 | length 153.5
  Top Layer w10: T2.2@976.38,1216.9 976.38,1271.65 1023.34,1318.61 ; 1023.62,1318.9 1023.34,1318.61 ; C80.2@1023.62,1350.39 1023.34,1350.11 1023.34,1318.61
BQ_FAULT_CC: R155.1 U1.14 U13.4 | length 1217.2
  Top Layer w7: R155.1@2708.66,1342.52 2708.66,1362.2 2744.09,1397.64 2826.77,1397.64 2867.78,1356.63 ; U1.14@2868.11,1059.06 2868.11,1094.08 2862.05,1100.14 2862.05,1264.8 2870.08,1272.84 v1(2870.08,1276.41) 2868.11,1278.37 2868.11,1356.63 ; v1@3307.09,1279.53 3342.52,1244.09 3448.82,1244.09 3500,1295.28 U13.4@3500,1326.77
  Bottom Layer w7: v1(2870.08,1276.41) 2953.37,1276.41 ; 2953.38,1276.41 3307.9,1276.41 v1@3311.02,1279.53
  other v1: 3308.32,1277.99
BUCK_OUT: C3.2 C5.1 L1.1 R3.2 R8.2 | length 332.2
  Top Layer w20: R3.2@1931.64,1660.74 2013.1,1660.74 C3.2@2015.75,1663.39 R8.2@2096.84,1663.39 ; R8.2@2096.84,1661.42 2129.92,1661.42 2159.61,1691.1 2163.54,1691.1 2165.35,1692.91 C5.1@2165.35,1696.85 2240.16,1696.85 L1.1@2244.09,1700.79
CB0: C67.2 C69.1 R106.2 R108.2 U2.39 | length 1611.9
  Top Layer w11.81: v2(1417.32,2566.93) 1460.63,2566.93 1478.35,2549.21 U2.39@1586.61,2549.21
  Bottom Layer w20: v2@645.67,3452.76 R108.2@645.67,3492.91 ; v2(649.61,3452.76) 649.22,3452.37 642.26,3452.37 629.92,3440.04 629.92,3090.55 1149.86,2570.61 1263.78,2570.61 C69.1@1263.78,2574.8 1295.28,2574.8 1311.02,2559.06 C67.2@1338.58,2559.06 ; C67.2@1334.65,2559.06 1377.95,2559.06 1385.83,2566.93 v2(1417.32,2566.93)
  other v2: 602.36,3452.76
CB1: C65.2 C67.1 R101.2 R104.2 U2.37 | length 1504.2
  Top Layer w11.81: v2(1417.32,2614.17) 1476.38,2614.17 1501.97,2588.58 U2.37@1586.61,2588.58
  Bottom Layer w20: R104.2@771.65,3496.06 v2(771.65,3452.76) 748.03,3429.13 748.03,3047.24 C65.2@1188.98,2606.3 1220.47,2606.3 1228.35,2614.17 1299.21,2614.17 1307.09,2622.05 C67.1@1338.58,2622.05 ; C67.1@1334.65,2622.05 1377.95,2622.05 1385.83,2614.17 v2(1417.32,2614.17)
  other v2: 724.41,3452.76
CB2: C63.2 C65.1 R97.2 R99.2 U2.35 | length 1403.4
  Top Layer w11.81: v2(1417.32,2661.42) 1492.13,2661.42 1525.59,2627.95 U2.35@1586.61,2627.95
  Bottom Layer w20: R99.2@866.14,3492.91 R99.2@866.14,3503.94 ; v2@885.83,3452.76 R99.2@885.83,3492.91 ; v2(889.76,3452.76) 866.14,3429.13 866.14,2992.13 C65.1@1188.98,2669.29 1216.54,2669.29 1232.28,2653.54 C63.2@1263.78,2653.54 ; C63.2@1259.84,2653.54 1299.21,2653.54 1307.09,2661.42 v2(1417.32,2661.42)
  other v2: 842.52,3452.76
CB3: C61.2 C63.1 R94.2 R96.2 U2.33 | length 1244.2
  Top Layer w11.81: v2(1417.32,2708.66) 1507.87,2708.66 1549.21,2667.32 U2.33@1586.61,2667.32
  Bottom Layer w20: R96.2@988.19,3492.91 988.19,2992.13 C63.1@1263.78,2716.54 1295.28,2716.54 1311.02,2700.79 C61.2@1338.58,2700.79 ; C61.2@1334.65,2700.79 1377.95,2700.79 1385.83,2708.66 v2(1417.32,2708.66)
  other v2: 964.57,3452.76 1014.81,3452.76
CB4: C57.2 C61.1 R91.2 R93.2 U2.31 | length 1612.3
  Top Layer w11.81: v2(1657.48,2913.39) 1657.48,2817.33 1683.07,2791.74 U2.31@1683.07,2744.09
  Bottom Layer w20: R91.2@1106.3,3496.06 1106.3,2996.06 C61.1@1338.58,2763.78 1338.58,2952.76 1381.89,2996.06 C57.2@1649.61,2996.06 1649.61,2952.76 1657.48,2944.88 v2(1657.48,2913.39)
  other v2: 1082.68,3452.76 1129.92,3452.76
CB5: C52.2 C57.1 R86.2 R89.2 U2.29 | length 1145.2
  Top Layer w11.81: v2(1704.72,2913.39) 1704.72,2826.77 1722.44,2809.06 U2.29@1722.44,2744.09
  Bottom Layer w20: R89.2@1232.28,3492.91 1232.28,3251.97 1314.96,3169.29 1633.86,3169.29 1696.85,3106.3 C52.2@1696.85,3070.87 1696.85,3039.37 1712.6,3023.62 C57.1@1712.6,2996.06 1712.6,2952.76 1704.72,2944.88 v2(1704.72,2913.39)
  other v2: 1208.66,3452.76 1255.91,3452.76
CB6: C47.2 C52.1 R81.2 R83.2 U2.27 | length 993.2
  Top Layer w11.81: v2(1751.97,2913.39) 1751.97,2834.65 1761.81,2824.8 U2.27@1761.81,2744.09
  Bottom Layer w20: R81.2@1350.39,3492.91 1350.39,3425.2 1523.62,3251.97 1637.8,3251.97 1734.41,3155.35 1734.41,3154.37 1743.11,3145.67 C47.2@1744.09,3145.67 1744.09,3114.17 1759.84,3098.43 1759.84,3031.5 1751.97,3023.62 v2(1751.97,2913.39)
  other v2: 1334.65,3452.76 1366.14,3452.76
CB7: C42.2 C47.1 C60.2 R74.2 R78.2 U2.25 | length 1682.6
  Top Layer w11.81: v2(1799.21,2913.39) 1799.21,2846.46 1801.18,2844.49 U2.25@1801.18,2744.09
  Bottom Layer w8: v2(1799.21,2913.39) 1799.21,2850.39 1870.08,2779.53 1933.07,2779.53 1944.88,2791.34 2007.87,2791.34 2021.21,2791.34 2085.7,2855.83 2176.25,2855.83 2195.19,2874.76 2299.96,2874.76 2330.71,2905.51 2330.71,3035.43 2311.02,3055.12 C60.2@2283.46,3055.12
  Bottom Layer w11.81: C42.2@1791.34,2996.06 1791.34,2952.76 1799.21,2944.88 v2(1799.21,2913.39)
  Bottom Layer w20: R78.2@1665.35,3496.06 1665.35,3334.65 1807.09,3192.91 C47.1@1807.09,3145.67 1807.09,3114.17 1799.21,3106.3 1799.21,3035.43 1791.34,3027.56 C42.2@1791.34,2996.06
  other v2: 1641.73,3452.76 1681.1,3452.76
CB8: C37.2 C42.1 C55.2 R69.2 R71.2 U2.23 | length 1372.6
  Top Layer w11.81: U2.23@1840.55,2744.09 1840.55,2860.24 1846.46,2866.14 v2(1846.46,2913.39)
  Bottom Layer w8: v2(1846.46,2913.39) 1846.46,2850.39 1885.83,2811.02 1917.32,2811.02 1929.13,2822.83 2007.87,2822.83 2070.87,2885.83 2161.42,2885.83 2181.1,2905.51 2279.53,2905.51 2283.46,2909.45 C55.2@2283.46,2937.01
  Bottom Layer w11.81: v2(1846.46,2913.39) 1846.46,2944.88 1854.33,2952.76 C42.1@1854.33,2996.06
  Bottom Layer w20: R71.2@1787.4,3492.13 1787.4,3251.97 1846.46,3192.91 1846.46,3110.24 1838.58,3102.36 C37.2@1838.58,3070.87 1838.58,3039.37 1854.33,3023.62 C42.1@1854.33,2996.06
  other v2: 1767.72,3452.76 1807.09,3452.76
CB9: C35.2 C37.1 C51.2 R65.2 R68.2 U2.21 | length 1021
  Top Layer w11.81: U2.21@1879.92,2744.09 1879.92,2844.49 1893.7,2858.27 v2(1893.7,2913.39)
  Bottom Layer w8: v2(1893.7,2913.39) 1917.32,2913.39 1933.07,2897.64 1960.63,2897.64 1976.38,2913.39 1988.19,2913.39 2003.73,2913.39 2042.06,2951.72 2042.06,2963.32 2047.24,2968.5 2066.93,2988.19 C51.2@2094.49,2988.19
  Bottom Layer w11.81: v2(1893.7,2913.39) 1893.7,3023.62 1901.57,3031.5 C37.1@1901.57,3070.87 C37.1@1899.64,3072.81
  Bottom Layer w20: C37.1@1899.64,3072.81 1899.64,3100.36 1885.83,3114.17 C35.2@1885.83,3145.67 1885.83,3192.91 1909.45,3216.54 R68.2@1909.45,3488.19
  other v2: 1889.76,3452.76 1929.13,3452.76
CB10: C33.2 C35.1 C48.2 R62.2 R64.2 U2.18 | length 1078.5
  Top Layer w11.81: U2.18@1938.98,2744.09 1938.98,2801.18 1948.82,2811.02 1948.82,2910.63 1940.94,2918.5 v2(1940.94,2921.26)
  Bottom Layer w7: v2(1940.94,2921.26) 1941.28,2921.59 1957.02,2921.59 1964.57,2929.13 1998.06,2929.13 2027.56,2958.64 2027.56,2997.86 2044.37,3014.67 2044.37,3028.62 2062.99,3047.24 2094.49,3078.74 C48.2@2094.49,3106.3
  Bottom Layer w11.81: C33.2@1933.07,2996.06 1933.07,2955.89 1938.99,2949.96 1938.99,2923.21 v2(1940.94,2921.26)
  Bottom Layer w20: C33.2@1933.07,2996.06 1933.07,3027.56 1940.94,3035.43 1940.94,3106.3 1948.82,3114.17 C35.1@1948.82,3145.67 2035.43,3232.28 R64.2@2035.43,3492.13
  other v2: 2015.75,3452.76 2055.12,3452.76
CB11: C31.2 C33.1 C45.2 R55.2 R59.2 U2.16 | length 1358.6
  Top Layer w11.81: v2(2000.56,2960.63) 2000.56,2912.83 v2(2204.72,2708.66) 2114.17,2708.66 2072.83,2667.32 U2.16@2035.43,2667.32
  Bottom Layer w11.81: C33.1@1996.06,2996.06 1996.06,2967.88 2000.56,2963.39 v2(2000.56,2960.63) ; v2(2204.72,2708.66) 2236.22,2708.66 2244.09,2716.54 C31.2@2283.46,2716.54 2354.33,2716.54 C45.2@2409.45,2771.65
  Bottom Layer w20: C33.1@1996.06,2996.06 2023.37,3023.37 2023.37,3168.35 2168.35,3313.33 R59.2@2168.35,3492.25
  other v2: 2149.61,3452.76 2188.98,3452.76
CB12: C29.2 C31.1 C41.2 R50.2 R52.2 U2.14 | length 2072.5
  Top Layer w11.81: U2.14@2035.43,2627.95 2096.46,2627.95 2129.92,2661.42 v2(2196.85,2661.42)
  Bottom Layer w8: v2(2196.85,2661.42) 2164.68,2661.42 2110.24,2715.86 2110.24,2747.81 2141.96,2779.53 2326.77,2779.53 2413.39,2866.14 2413.39,2960.63 2432.02,2979.26 2467.45,2979.26 C41.2@2468.5,2980.32
  Bottom Layer w11.81: v2(2196.85,2661.42) 2236.22,2661.42 2244.09,2653.54 C31.1@2287.4,2653.54
  Bottom Layer w20: R52.2@2283.05,3491.71 2286.82,3491.71 2309.88,3468.64 2309.88,3464.87 2618.11,3156.65 2618.11,2929.13 C29.2@2358.27,2669.29 2326.77,2669.29 2311.02,2653.54 C31.1@2283.46,2653.54
  other v2: 2267.72,3452.76 2303.15,3452.76
CB13: C27.2 C29.1 C38.2 R43.2 R47.2 U2.12 | length 2222.6
  Top Layer w11.81: U2.12@2035.43,2588.58 2120.08,2588.58 2145.67,2614.17 v2(2192.91,2614.17)
  Bottom Layer w8: v2(2192.91,2614.17) 2166.91,2614.2 2078.43,2702.68 2078.43,2760.98 2128.62,2811.18 2312.31,2811.18 2381.89,2880.76 2381.89,3047.24 2429.17,3094.53 C38.2@2456.69,3094.53
  Bottom Layer w11.81: v2(2192.91,2614.17) 2314.96,2614.17 2322.83,2606.3
  Bottom Layer w20: 2322.83,2606.3 2385.83,2606.3 2401.57,2622.05 C27.2@2433.07,2622.05 2693.5,2882.48 R47.2@2693.5,3495.42
  other v2: 2669.29,3452.76 2712.6,3452.76
CB14: C25.2 C27.1 R40.2 R42.2 U2.10 | length 1504.4
  Top Layer w11.81: U2.10@2035.43,2549.21 2143.7,2549.21 2161.42,2566.93 v2(2204.72,2566.93)
  Bottom Layer w11.81: v2(2204.72,2566.93) 2236.22,2566.93 2244.09,2574.8 C25.2@2283.46,2574.8
  Bottom Layer w20: C25.2@2283.46,2574.8 2314.96,2574.8 2322.83,2566.93 2393.7,2566.93 2401.57,2559.06 C27.1@2433.07,2559.06 2811.02,2937.01 R42.2@2811.02,3492.13
  other v2: 2791.34,3452.76 2830.71,3452.76
CB15: C23.2 C25.1 R37.2 R39.2 U2.8 | length 1609.5
  Top Layer w11.81: U2.8@2035.43,2509.84 2166.17,2509.84 2176.01,2519.68 v2(2204.72,2519.68)
  Bottom Layer w11.81: v2(2204.72,2519.68) 2236.22,2519.68 2244.09,2511.81 C25.1@2283.46,2511.81
  Bottom Layer w20: C25.1@2283.46,2511.81 2311.02,2511.81 2326.77,2527.56 C23.2@2358.27,2527.56 2393.7,2527.56 2401.57,2519.68 2460.63,2519.68 2921.26,2980.32 R39.2@2921.26,3496.06
  other v2: 2905.51,3452.76 2944.88,3452.76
